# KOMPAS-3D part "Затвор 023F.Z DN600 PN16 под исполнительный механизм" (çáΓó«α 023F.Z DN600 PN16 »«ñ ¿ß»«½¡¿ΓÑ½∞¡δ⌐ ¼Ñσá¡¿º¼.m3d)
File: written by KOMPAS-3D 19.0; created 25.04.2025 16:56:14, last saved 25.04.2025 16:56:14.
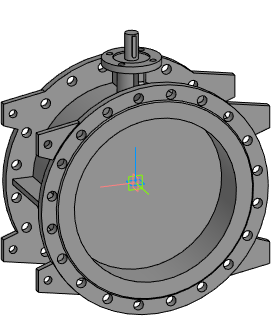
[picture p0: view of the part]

Document properties: Автор: Евгений; Полное имя файла: E:\Dendor Работа Сачек\3D для проекитирвщиков\1.7 Тип 023F.Z Затвор дисковый поворотный фланцевый с двумя эксцентриками\stp_Тип 023F.Z. Затвор под исполн. механизм\Затвор 023F.Z DN600 PN16 под исполнительный механизм.m3d

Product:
- Part/product: Затвор 023F.Z DN600 PN16 под исполнительный механизм

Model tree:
1. Операция без истории:1  (labels: Затвор 023F.Z DN600 PN16 под исполнительный механизм)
